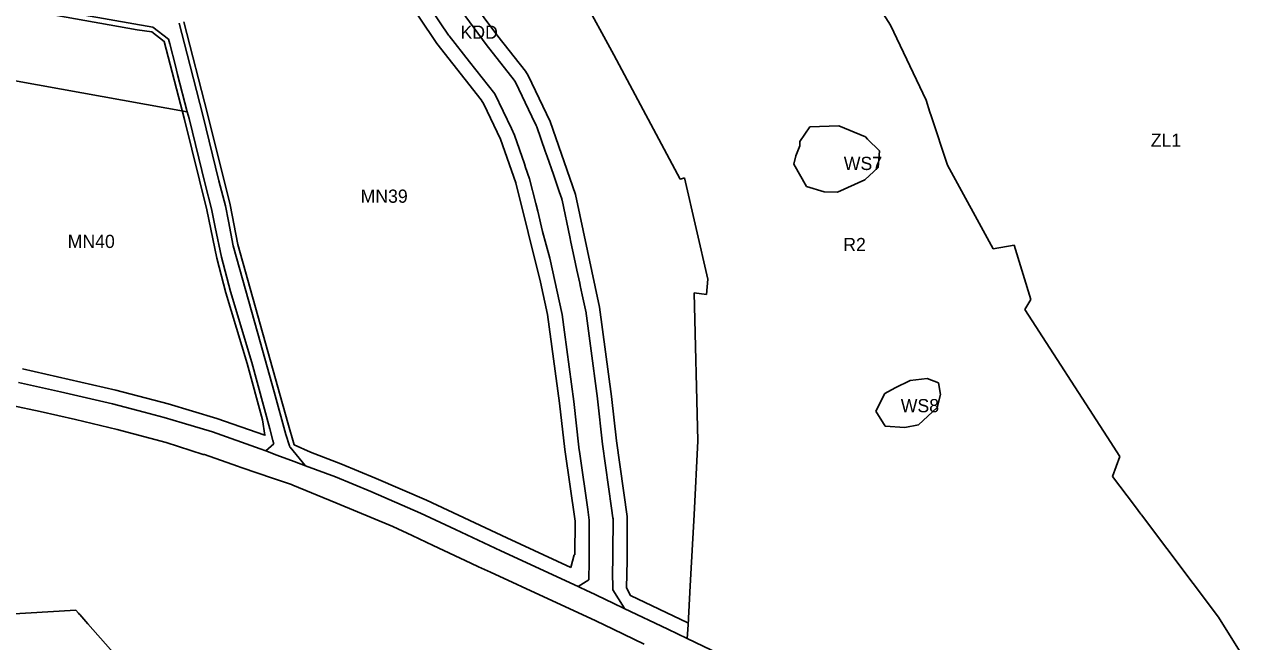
# Model space of a CAD drawing. Extents: x 7428103 to 7431580, y 5545880 to 5549002.
# Drawn here: x 7430217 to 7430734, y 5546653 to 5546912 of the extents above; entities that cross this region are included whole.
import ezdxf

# ---------------------------------------------------------------- set-up
doc = ezdxf.new("R2010")
doc.units = 0
for name, color, linetype in [('CZ_L_linie rozgraniczające tereny o różnym przeznaczeniu oraz różnych warunkach ich zabudowy i zagospodarowania', 7, 'Continuous'), ('CZ_L_maksymalne nieprzekraczalne linie zabudowy', 7, 'Continuous'), ('CZ_L_opisy_linie rozgraniczające tereny o różnym przeznaczeniu oraz różnych warunkach ich zabudowy i zagospodarowania', 7, 'Continuous')]:
    doc.layers.add(name, color=color, linetype=linetype)

msp = doc.modelspace()

# ---------------------------------------------------------------- linework, layer by layer
at = {"layer": 'CZ_L_linie rozgraniczające tereny o różnym przeznaczeniu oraz różnych warunkach ich zabudowy i zagospodarowania'}
for p, q in [((7430445.69, 5546934.1), (7430464.79, 5546899.07)), ((7430271.15, 5546910.68), (7430161.61, 5546930.19)), ((7430384.6, 5546923.5), (7430395.32, 5546907.4)), ((7430581.04, 5546911.62), (7430571.79, 5546926.26)), ((7430411.21, 5546903.4), (7430399.09, 5546919.79)), ((7430285.53, 5546899.31), (7430282.23, 5546912.41)), ((7430595.96, 5546880.01), (7430581.04, 5546911.62)), ((7430277.75, 5546905.67), (7430271.15, 5546910.68)), ((7430395.32, 5546907.4), (7430395.45, 5546907.25)), ((7430395.45, 5546907.25), (7430395.56, 5546907.08)), ((7430395.56, 5546907.08), (7430404.19, 5546896.15)), ((7430129.8, 5546903.11), (7430285.61, 5546875.17)), ((7430278.22, 5546903.78), (7430277.75, 5546905.67)), ((7430280.6, 5546894.5), (7430278.22, 5546903.78)), ((7430411.21, 5546903.39), (7430411.21, 5546903.4)), ((7430422.95, 5546888.51), (7430411.21, 5546903.39)), ((7430292.17, 5546873.78), (7430285.53, 5546899.31)), ((7430404.19, 5546896.15), (7430414.75, 5546882.76)), ((7430464.79, 5546899.07), (7430492.69, 5546846.82)), ((7430281.52, 5546890.89), (7430280.6, 5546894.5)), ((7430285.61, 5546875.17), (7430281.52, 5546890.89)), ((7430423.49, 5546887.63), (7430422.95, 5546888.51)), ((7430423.54, 5546887.57), (7430423.49, 5546887.63)), ((7430430.4, 5546873.19), (7430423.54, 5546887.57)), ((7430414.75, 5546882.76), (7430421.74, 5546868.13)), ((7430597.61, 5546874.97), (7430595.96, 5546880.01)), ((7430286.34, 5546872.35), (7430285.61, 5546875.17)), ((7430598.12, 5546873.44), (7430597.61, 5546874.97)), ((7430293.07, 5546844.77), (7430286.34, 5546872.35)), ((7430298.9, 5546846.18), (7430292.17, 5546873.78)), ((7430432.22, 5546869.39), (7430430.4, 5546873.19)), ((7430604.93, 5546852.65), (7430598.12, 5546873.44)), ((7430421.74, 5546868.13), (7430423.07, 5546865.33)), ((7430423.07, 5546865.33), (7430427.23, 5546853.34)), ((7430432.22, 5546869.36), (7430432.22, 5546869.39)), ((7430432.24, 5546869.33), (7430432.22, 5546869.36)), ((7430432.43, 5546868.87), (7430432.24, 5546869.33)), ((7430435.97, 5546858.66), (7430432.43, 5546868.87)), ((7430542.88, 5546862.67), (7430547.1, 5546868.79)), ((7430547.1, 5546868.79), (7430559.36, 5546869.29)), ((7430559.36, 5546869.29), (7430570.47, 5546864.59)), ((7430570.47, 5546864.59), (7430571.39, 5546863.69)), ((7430541.2, 5546856.58), (7430542.89, 5546860.87)), ((7430542.89, 5546860.87), (7430542.88, 5546862.67)), ((7430571.39, 5546863.69), (7430571.32, 5546863.66)), ((7430571.32, 5546863.66), (7430576.35, 5546858.78)), ((7430436.79, 5546856.3), (7430435.97, 5546858.66)), ((7430439.4, 5546848.74), (7430436.79, 5546856.3)), ((7430540.35, 5546853.13), (7430541.2, 5546856.58)), ((7430576.35, 5546858.78), (7430575.9, 5546851.69)), ((7430427.23, 5546853.34), (7430427.6, 5546852.28)), ((7430427.54, 5546852.17), (7430427.52, 5546852.11)), ((7430427.52, 5546852.11), (7430427.53, 5546852.1)), ((7430427.53, 5546852.1), (7430429.4, 5546846.99)), ((7430427.6, 5546852.28), (7430427.54, 5546852.17)), ((7430545.76, 5546843.77), (7430540.35, 5546853.13)), ((7430575.9, 5546851.69), (7430570.27, 5546846.56)), ((7430624.12, 5546817.56), (7430604.93, 5546852.65)), ((7430295.74, 5546834.35), (7430293.07, 5546844.77)), ((7430301.61, 5546835.59), (7430298.9, 5546846.18)), ((7430429.4, 5546846.99), (7430431.98, 5546836.56)), ((7430441.88, 5546841.59), (7430439.4, 5546848.74)), ((7430492.69, 5546846.82), (7430493.27, 5546847.01)), ((7430493.27, 5546847.01), (7430494.45, 5546847.39)), ((7430494.45, 5546847.39), (7430504.23, 5546804.78)), ((7430553.17, 5546841.52), (7430545.76, 5546843.77)), ((7430570.27, 5546846.56), (7430558.76, 5546841.32)), ((7430442.93, 5546838.58), (7430441.88, 5546841.59)), ((7430442.97, 5546838.34), (7430442.93, 5546838.58)), ((7430558.76, 5546841.32), (7430553.17, 5546841.52)), ((7430297.25, 5546826.67), (7430295.74, 5546834.35)), ((7430302.88, 5546829.14), (7430301.61, 5546835.59)), ((7430431.98, 5546836.56), (7430432.81, 5546833.4)), ((7430432.81, 5546833.4), (7430434.88, 5546824.86)), ((7430443.1, 5546837.95), (7430442.97, 5546838.34)), ((7430446.27, 5546822.58), (7430443.1, 5546837.95)), ((7430304.91, 5546818.87), (7430302.88, 5546829.14)), ((7430299.96, 5546814.1), (7430297.25, 5546826.67)), ((7430434.88, 5546824.86), (7430437.96, 5546813.59)), ((7430315.22, 5546781.95), (7430304.91, 5546818.87)), ((7430446.72, 5546820.39), (7430446.27, 5546822.58)), ((7430448.12, 5546813.94), (7430446.72, 5546820.39)), ((7430632.98, 5546819.11), (7430624.17, 5546817.48)), ((7430639.93, 5546796.26), (7430632.98, 5546819.11)), ((7430303.78, 5546799.62), (7430299.96, 5546814.1)), ((7430437.96, 5546813.59), (7430443.09, 5546790.01)), ((7430449.28, 5546808.59), (7430448.12, 5546813.94)), ((7430624.17, 5546817.48), (7430624.12, 5546817.56)), ((7430450.47, 5546803.12), (7430449.28, 5546808.59)), ((7430450.68, 5546802.14), (7430450.47, 5546803.12)), ((7430504.23, 5546804.78), (7430503.68, 5546798.39)), ((7430312.67, 5546769.83), (7430303.78, 5546799.62)), ((7430451.54, 5546798.17), (7430450.68, 5546802.14)), ((7430452.9, 5546791.93), (7430451.54, 5546798.17)), ((7430503.68, 5546798.39), (7430498.61, 5546799.08)), ((7430498.61, 5546799.08), (7430500.13, 5546736.91)), ((7430637.45, 5546792), (7430639.93, 5546796.26)), ((7430443.09, 5546790.01), (7430444.09, 5546782.5)), ((7430452.94, 5546791.65), (7430452.9, 5546791.93)), ((7430452.97, 5546791.54), (7430452.94, 5546791.65)), ((7430454.95, 5546776.73), (7430452.97, 5546791.54)), ((7430672.02, 5546738.56), (7430637.45, 5546792)), ((7430322.08, 5546757.38), (7430315.22, 5546781.95)), ((7430444.09, 5546782.5), (7430447.99, 5546753.4)), ((7430457.91, 5546754.67), (7430454.95, 5546776.73)), ((7430320.29, 5546741.83), (7430312.67, 5546769.83)), ((7430214.71, 5546761.39), (7430232.33, 5546757.46)), ((7430582.93, 5546759.16), (7430589.32, 5546762.27)), ((7430589.32, 5546762.27), (7430596.42, 5546763.05)), ((7430596.42, 5546763.05), (7430601.15, 5546761.26)), ((7430601.15, 5546761.26), (7430601.97, 5546756.27)), ((7430232.33, 5546757.46), (7430254.17, 5546752.37)), ((7430327.06, 5546739.54), (7430322.08, 5546757.38)), ((7430574.9, 5546749.28), (7430578.63, 5546756.75)), ((7430578.63, 5546756.75), (7430582.93, 5546759.16)), ((7430601.97, 5546756.27), (7430600.64, 5546750.88)), ((7430223.76, 5546749.13), (7430211.96, 5546751.76)), ((7430254.17, 5546752.37), (7430267.43, 5546748.93)), ((7430447.99, 5546753.4), (7430450.09, 5546734.22)), ((7430457.92, 5546754.57), (7430457.91, 5546754.67)), ((7430457.92, 5546754.55), (7430457.92, 5546754.57)), ((7430460.02, 5546735.39), (7430457.92, 5546754.55)), ((7430600.64, 5546750.88), (7430592.75, 5546743.55)), ((7430238.61, 5546745.81), (7430223.76, 5546749.13)), ((7430256.11, 5546741.62), (7430238.61, 5546745.81)), ((7430267.43, 5546748.93), (7430275.9, 5546746.65)), ((7430275.9, 5546746.65), (7430283.5, 5546744.4)), ((7430578.75, 5546743.04), (7430574.9, 5546749.28)), ((7430276.68, 5546736.09), (7430256.11, 5546741.62)), ((7430283.5, 5546744.4), (7430296.15, 5546740.59)), ((7430296.15, 5546740.59), (7430316.22, 5546733.53)), ((7430321.6, 5546737.01), (7430320.29, 5546741.83)), ((7430587.03, 5546742.39), (7430578.75, 5546743.04)), ((7430592.75, 5546743.55), (7430587.03, 5546742.39)), ((7430292.22, 5546731.1), (7430276.68, 5546736.09)), ((7430318.61, 5546732.63), (7430321.98, 5546735.63)), ((7430321.98, 5546735.63), (7430321.6, 5546737.01)), ((7430328.53, 5546734.68), (7430327.06, 5546739.54)), ((7430463.86, 5546708.56), (7430460.02, 5546735.39)), ((7430500.13, 5546736.91), (7430498.5, 5546705.67)), ((7430677.34, 5546730.32), (7430672.02, 5546738.56)), ((7430292.8, 5546731.16), (7430292.22, 5546731.1)), ((7430306.72, 5546726.22), (7430292.8, 5546731.16)), ((7430316.22, 5546733.53), (7430318.61, 5546732.63)), ((7430318.61, 5546732.63), (7430323.27, 5546730.88)), ((7430323.27, 5546730.88), (7430330.5, 5546728.16)), ((7430328.66, 5546734.24), (7430328.53, 5546734.68)), ((7430328.77, 5546734.16), (7430328.66, 5546734.24)), ((7430335.19, 5546726.44), (7430328.77, 5546734.16)), ((7430450.09, 5546734.22), (7430450.1, 5546734.19)), ((7430450.1, 5546734.19), (7430450.11, 5546734.05)), ((7430450.11, 5546734.05), (7430450.49, 5546731.4)), ((7430450.49, 5546731.4), (7430453.84, 5546708.04)), ((7430674.33, 5546721.9), (7430677.34, 5546730.32)), ((7430306.75, 5546726.21), (7430306.72, 5546726.22)), ((7430306.77, 5546726.2), (7430306.75, 5546726.21)), ((7430308.28, 5546725.68), (7430306.77, 5546726.2)), ((7430321.78, 5546721.06), (7430308.28, 5546725.68)), ((7430330.5, 5546728.16), (7430335.2, 5546726.4)), ((7430335.2, 5546726.4), (7430335.19, 5546726.44)), ((7430335.2, 5546726.4), (7430347.84, 5546721.64)), ((7430329.45, 5546718.44), (7430321.78, 5546721.06)), ((7430347.84, 5546721.64), (7430362.68, 5546715.5)), ((7430680.46, 5546713.79), (7430674.33, 5546721.9)), ((7430329.98, 5546718.22), (7430329.45, 5546718.44)), ((7430347.99, 5546710.76), (7430329.98, 5546718.22)), ((7430362.68, 5546715.5), (7430383.59, 5546706.43)), ((7430372.01, 5546700.82), (7430347.99, 5546710.76)), ((7430683.95, 5546709.15), (7430680.46, 5546713.79)), ((7430383.59, 5546706.43), (7430398.24, 5546699.55)), ((7430453.84, 5546708.04), (7430454.49, 5546703.49)), ((7430464.44, 5546704.54), (7430463.86, 5546708.56)), ((7430464.49, 5546704.03), (7430464.44, 5546704.54)), ((7430498.5, 5546705.67), (7430496.87, 5546675.88)), ((7430684, 5546709.09), (7430683.95, 5546709.15)), ((7430686.23, 5546706.05), (7430684, 5546709.09)), ((7430686.46, 5546705.76), (7430686.23, 5546706.05)), ((7430718.79, 5546662.69), (7430686.46, 5546705.76)), ((7430380.06, 5546697.04), (7430372.01, 5546700.82)), ((7430398.24, 5546699.55), (7430417.29, 5546690.62)), ((7430454.49, 5546703.49), (7430454.43, 5546692.57)), ((7430464.41, 5546690.15), (7430464.49, 5546703.8)), ((7430464.47, 5546703.91), (7430464.49, 5546704.03)), ((7430464.49, 5546703.8), (7430464.47, 5546703.91)), ((7430388.91, 5546692.89), (7430380.06, 5546697.04)), ((7430404.69, 5546685.48), (7430388.91, 5546692.89)), ((7430417.29, 5546690.62), (7430449.81, 5546675.6)), ((7430454.43, 5546692.57), (7430454.39, 5546686.69)), ((7430464.39, 5546686.59), (7430464.41, 5546690.15)), ((7430408, 5546683.93), (7430404.69, 5546685.48)), ((7430412.94, 5546681.61), (7430408, 5546683.93)), ((7430454.37, 5546685.62), (7430454.33, 5546679.17)), ((7430454.39, 5546686.69), (7430454.37, 5546685.62)), ((7430464.27, 5546681.92), (7430464.39, 5546686.48)), ((7430464.38, 5546686.53), (7430464.39, 5546686.59)), ((7430464.39, 5546686.48), (7430464.38, 5546686.53)), ((7430412.96, 5546681.6), (7430412.94, 5546681.61)), ((7430412.97, 5546681.6), (7430412.96, 5546681.6)), ((7430437.25, 5546670.4), (7430412.97, 5546681.6)), ((7430454.33, 5546678.46), (7430449.81, 5546675.6)), ((7430454.33, 5546679.17), (7430454.33, 5546678.46)), ((7430464.44, 5546674.47), (7430464.27, 5546681.92)), ((7430449.81, 5546675.6), (7430453.9, 5546673.71)), ((7430453.9, 5546673.71), (7430454.3, 5546673.52)), ((7430454.3, 5546673.52), (7430464.57, 5546668.61)), ((7430464.44, 5546674.2), (7430464.44, 5546674.47)), ((7430469.14, 5546666.58), (7430464.44, 5546674.2)), ((7430496.87, 5546675.88), (7430495.96, 5546659.48)), ((7430453.36, 5546662.94), (7430437.25, 5546670.4)), ((7430464.57, 5546668.61), (7430469.16, 5546666.42)), ((7430208.3, 5546663.85), (7430238.8, 5546665.66)), ((7430238.8, 5546665.66), (7430239.96, 5546664.34)), ((7430239.96, 5546664.34), (7430240.24, 5546664.03)), ((7430240.24, 5546664.03), (7430240.44, 5546663.8)), ((7430240.44, 5546663.8), (7430243.87, 5546659.91)), ((7430457.18, 5546661.17), (7430453.36, 5546662.94)), ((7430469.16, 5546666.42), (7430469.14, 5546666.58)), ((7430487.53, 5546657.63), (7430469.16, 5546666.42)), ((7430243.87, 5546659.91), (7430268.68, 5546631.79)), ((7430464.49, 5546657.64), (7430457.18, 5546661.17)), ((7430477.54, 5546651.35), (7430464.49, 5546657.64)), ((7430495.65, 5546653.72), (7430487.53, 5546657.63)), ((7430495.96, 5546659.44), (7430495.65, 5546653.72)), ((7430495.96, 5546659.48), (7430495.96, 5546659.44)), ((7430734.32, 5546637.88), (7430718.79, 5546662.69)), ((7430495.65, 5546653.72), (7430509.05, 5546647.25))]:
    msp.add_line(p, q, dxfattribs=at)
at = {"layer": 'CZ_L_maksymalne nieprzekraczalne linie zabudowy'}
for points in [[(7430255.27, 5547122.04), (7430255.22, 5547118.96), (7430274.72, 5547102.13), (7430336.52, 5547041.58), (7430339.32, 5547038.18), (7430351.81, 5547021.26), (7430356.67, 5547011.75), (7430363.71, 5546993.43), (7430373.05, 5546972.78), (7430381.25, 5546957.03), (7430404.58, 5546922.46), (7430416.08, 5546906.9), (7430427.66, 5546892.23), (7430428.81, 5546890.43), (7430438, 5546871.09), (7430448.65, 5546840.38), (7430458.81, 5546792.97), (7430463.86, 5546755.45), (7430465.89, 5546736.87), (7430470.41, 5546705.09), (7430470.39, 5546686.55), (7430470.1, 5546675.12), (7430471.75, 5546671.83), (7430495.88, 5546660.27)], [(7430216.39, 5546767.17), (7430255.6, 5546758.2), (7430277.54, 5546752.43), (7430298.01, 5546746.29), (7430318.21, 5546739.19), (7430317.16, 5546745.72), (7430310.75, 5546769.28), (7430301.85, 5546799.08), (7430298.02, 5546813.63), (7430293.79, 5546833.91), (7430284.4, 5546871.86), (7430275.92, 5546904.73), (7430270.67, 5546908.79), (7430264.52, 5546909.65), (7430230.85, 5546915.6), (7430156.13, 5546929.21)], [(7430446.76, 5546683.62), (7430448.19, 5546688.86), (7430448.4, 5546688.99), (7430448.49, 5546703.07), (7430444.17, 5546733.21), (7430442.03, 5546752.68), (7430436.96, 5546789.95), (7430434, 5546803.59), (7430423.64, 5546845.27), (7430417.23, 5546863.65), (7430410.2, 5546878.37), (7430409.13, 5546880.19), (7430390.48, 5546903.87), (7430375.93, 5546925.7)], [(7430284.17, 5546912.9), (7430294.11, 5546874.27), (7430303.56, 5546836.04), (7430306.86, 5546819.33), (7430327.79, 5546744.38), (7430330.54, 5546735.23), (7430337.31, 5546732.01), (7430350.05, 5546727.22), (7430365.02, 5546721.03), (7430386.06, 5546711.9), (7430419.82, 5546696.06), (7430446.76, 5546683.62)]]:
    msp.add_lwpolyline(points, dxfattribs=at)

# ---------------------------------------------------------------- texts
at = {"layer": 'CZ_L_opisy_linie rozgraniczające tereny o różnym przeznaczeniu oraz różnych warunkach ich zabudowy i zagospodarowania'}
for s, p in [('KDD', (7430400.39, 5546905.85)), ('ZL1', (7430690.36, 5546860.45)), ('WS7', (7430561.41, 5546850.67)), ('MN39', (7430358.42, 5546836.91)), ('MN40', (7430235.36, 5546817.9)), ('R2', (7430561.18, 5546816.58)), ('WS8', (7430585.34, 5546748.86))]:
    msp.add_text(s, height=5.549, dxfattribs=at).set_placement(p)

doc.saveas('drawing.dxf')
